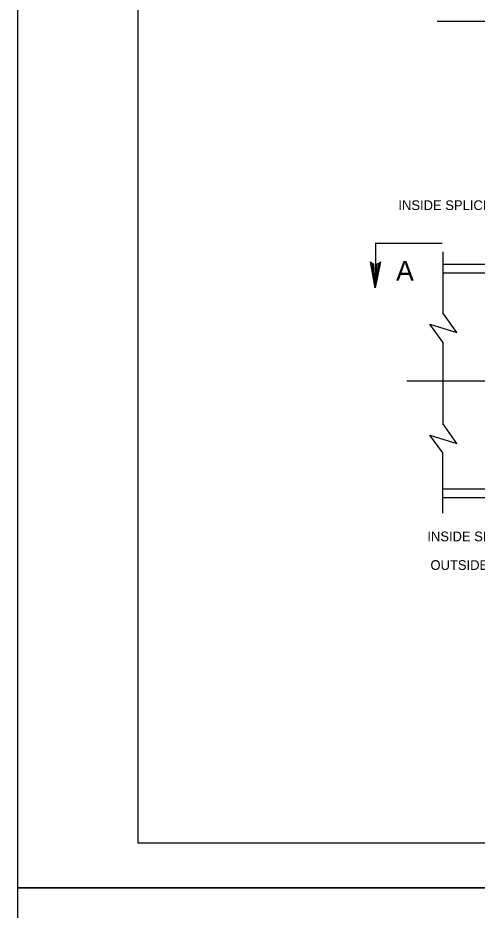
# Model space of a CAD drawing. Extents: x 638466 to 639375, y 297808 to 298996.
# Drawn here: x 638466 to 638619.3, y 298395 to 298692.8 of the extents above; entities that cross this region are included whole.
import ezdxf

# ---------------------------------------------------------------- set-up
doc = ezdxf.new("R2010")
doc.units = 0
for name, color, linetype in [('1', 7, 'Continuous'), ('2', 7, 'Continuous'), ('4', 7, 'Continuous'), ('PLT-BNDY', 7, 'Continuous')]:
    doc.layers.add(name, color=color, linetype=linetype)

msp = doc.modelspace()

# ---------------------------------------------------------------- linework, layer by layer
at = {"layer": '1'}
for p, q in [((638505.96, 298981.46), (638505.96, 298417.46)), ((638505.96, 298417.46), (639291.96, 298417.46))]:
    msp.add_line(p, q, dxfattribs=at)
msp.add_lwpolyline([(638586.53, 298610.97), (638585.81, 298610.66), (638585.28, 298602.73), (638586.53, 298610.97), (638586.96, 298611.39), (638585.28, 298602.73), (638584.82, 298610.65), (638584.11, 298610.95), (638585.28, 298602.73), (638583.63, 298611.39), (638584.11, 298610.95)], dxfattribs=at)
at = {"layer": '2'}
for p, q in [((638607.78, 298614.72), (638607.78, 298594.42)), ((638607.78, 298610.65), (638804.7, 298610.65)), ((638607.78, 298607.7), (638804.7, 298607.7)), ((638612.5, 298587.77), (638607.78, 298594.42)), ((638607.78, 298584.63), (638603.51, 298590.62)), ((638603.51, 298590.62), (638612.5, 298587.77)), ((638607.78, 298584.63), (638607.78, 298557.37)), ((638612.5, 298550.72), (638607.78, 298557.37)), ((638607.77, 298547.58), (638603.51, 298553.57)), ((638603.51, 298553.57), (638612.5, 298550.72)), ((638607.78, 298527.54), (638607.78, 298547.59)), ((638607.78, 298535.65), (638804.7, 298535.65)), ((638607.78, 298532.69), (638804.7, 298532.69))]:
    msp.add_line(p, q, dxfattribs=at)
at = {"layer": '4'}
for p, q in [((638825.25, 298691.61), (638605.94, 298691.61)), ((638607.54, 298617.57), (638585.28, 298617.57)), ((638585.43, 298605.01), (638585.43, 298617.72)), ((638595.76, 298571.68), (638629.71, 298571.68))]:
    msp.add_line(p, q, dxfattribs=at)
at = {"layer": 'PLT-BNDY'}
for points in [[(638465.96, 298996.46), (639306.96, 298996.46), (639306.96, 298402.46), (638465.96, 298402.46)], [(638465.96, 298402.46), (639306.96, 298402.46), (639306.96, 297808.46), (638465.96, 297808.46)]]:
    msp.add_lwpolyline(points, close=True, dxfattribs=at)

# ---------------------------------------------------------------- texts
at = {"layer": '4'}
for s, height, p in [('INSIDE SPLICE PLATE', 3.2401, (638592.98, 298628.69)), ('A', 6.61, (638592.22, 298605.11)), ('INSIDE SPLICE PLATE', 3.2401, (638602.64, 298518.11)), ('OUTSIDE SPLICE PLATE', 3.2401, (638603.69, 298508.55))]:
    msp.add_text(s, height=height, dxfattribs=at).set_placement(p)

doc.saveas('drawing.dxf')
